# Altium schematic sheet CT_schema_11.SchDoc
size 391 x 385 mm
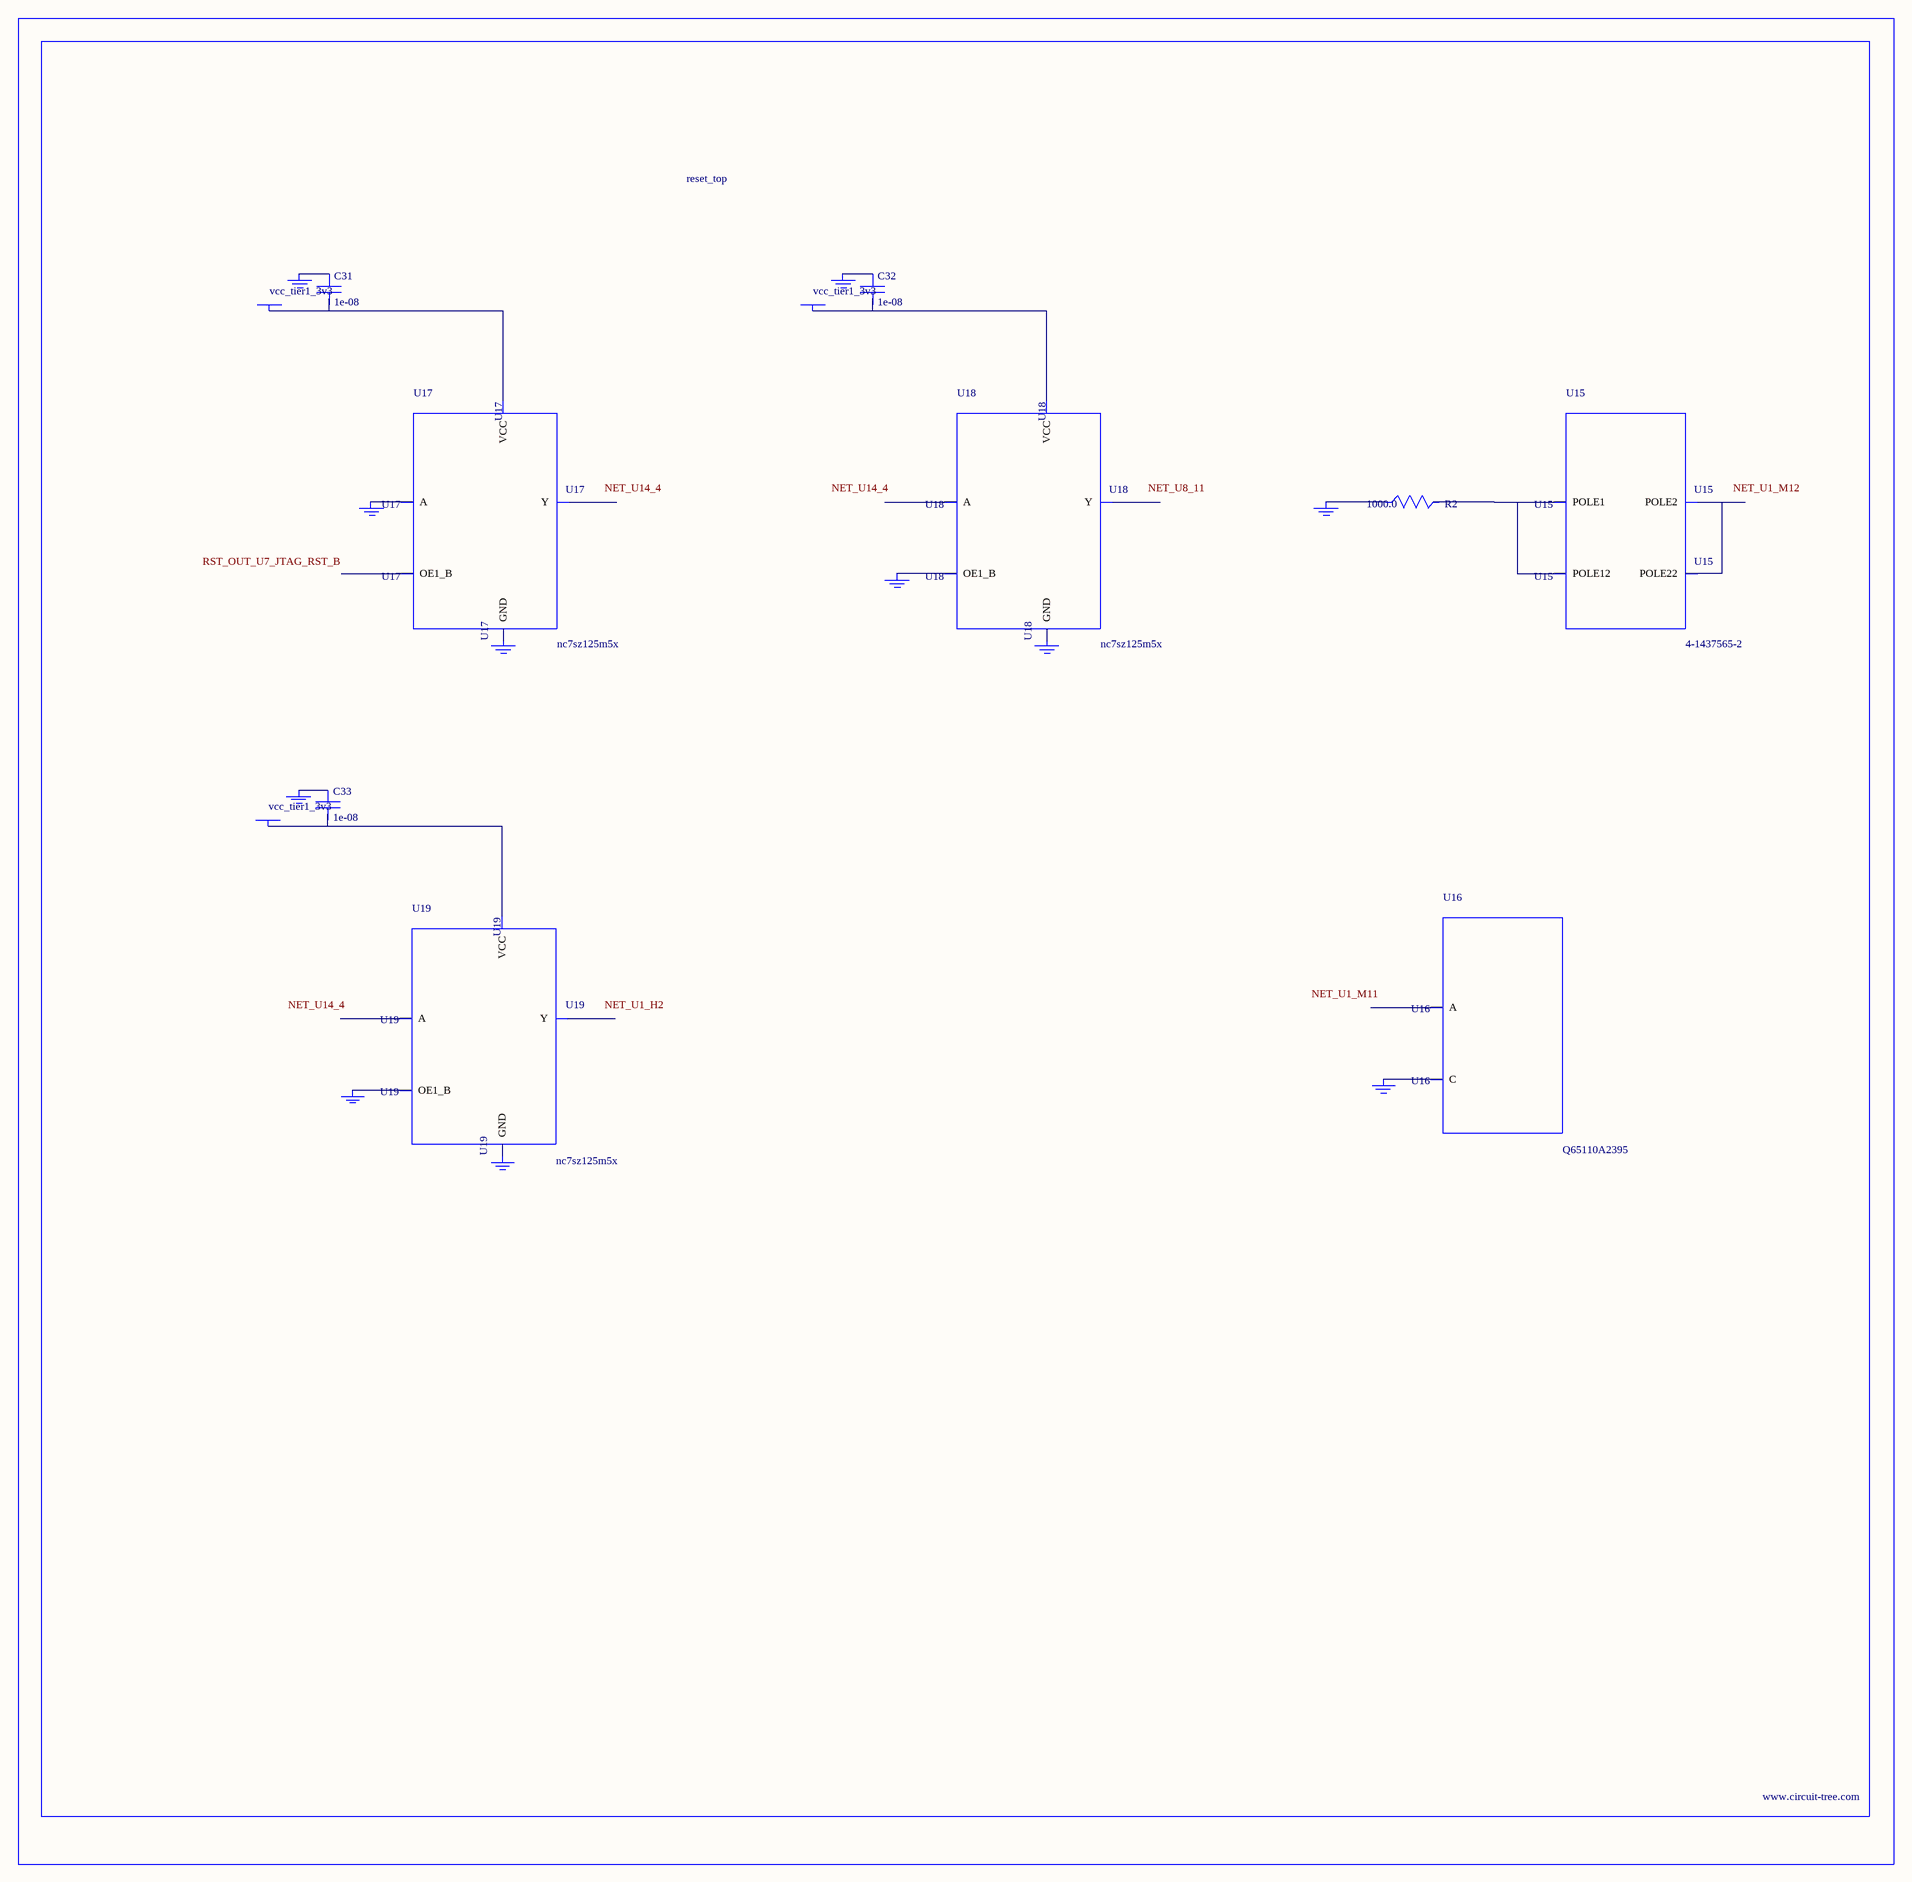
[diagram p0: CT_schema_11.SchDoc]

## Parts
BORDER10  (no value)
C31  1e-08  [C0402]
C32  1e-08  [C0402]
C33  1e-08  [C0402]
GND_INSTANCE_10_0  (no value)
GND_INSTANCE_10_1  (no value)
GND_INSTANCE_10_2  (no value)
GND_INSTANCE_10_3  (no value)
GND_INSTANCE_10_4  (no value)
GND_INSTANCE_10_5  (no value)
GND_INSTANCE_10_6  (no value)
GND_INSTANCE_10_7  (no value)
GND_INSTANCE_10_8  (no value)
GND_INSTANCE_10_9  (no value)
GND_INSTANCE_10_10  (no value)
POWER_INSTANCE_10_0  vcc_tier1_3v3
POWER_INSTANCE_10_1  vcc_tier1_3v3
POWER_INSTANCE_10_2  vcc_tier1_3v3
R2  1000.0  [R0603]
U15  4-1437565-2  [SW_4-1437565-2]
U16  Q65110A2395  [LGM67K-G1J2-24-Z]
U17  nc7sz125m5x  [NC7SZ125M5X]
U18  nc7sz125m5x  [NC7SZ125M5X]
U19  nc7sz125m5x  [NC7SZ125M5X]

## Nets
NetC31_1: C31.1 GND_INSTANCE_10_2.0(GND)
NetC31_2: C31.2 POWER_INSTANCE_10_0.0(PWR) U17.5(VCC)
NetC32_1: C32.1 GND_INSTANCE_10_5.0(GND)
NetC32_2: C32.2 POWER_INSTANCE_10_1.0(PWR) U18.5(VCC)
NetC33_1: C33.1 GND_INSTANCE_10_8.0(GND)
NetC33_2: C33.2 POWER_INSTANCE_10_2.0(PWR) U19.5(VCC)
NetGND_INSTANCE_10_0_0: GND_INSTANCE_10_0.0(GND) R2.1
NetGND_INSTANCE_10_1_0: GND_INSTANCE_10_1.0(GND) U16.C
NetGND_INSTANCE_10_3_0: GND_INSTANCE_10_3.0(GND) U17.2(A)
NetGND_INSTANCE_10_4_0: GND_INSTANCE_10_4.0(GND) U17.3(GND)
NetGND_INSTANCE_10_6_0: GND_INSTANCE_10_6.0(GND) U18.1(OE1_B)
NetGND_INSTANCE_10_7_0: GND_INSTANCE_10_7.0(GND) U18.3(GND)
NetGND_INSTANCE_10_9_0: GND_INSTANCE_10_9.0(GND) U19.1(OE1_B)
NetGND_INSTANCE_10_10_0: GND_INSTANCE_10_10.0(GND) U19.3(GND)
NetR2_2: R2.2 U15.1(POLE1) U15.2(POLE12)
NetU15_3: U15.3(POLE2) U15.4(POLE22)

Not connected (* = marked no-connect by the designer): U16 A; U17 1(OE1_B) 4(Y); U18 2(A) 4(Y); U19 2(A) 4(Y)

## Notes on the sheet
- Labels drawn without touching a wire or pin: NET_U1_H2, NET_U1_M11, NET_U1_M12, NET_U8_11, NET_U14_4, RST_OUT_U7_JTAG_RST_B

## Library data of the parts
BORDER10 = BORDER_PAGE10
C31-C33 = C0402C103K3RAC
GND_INSTANCE_10_0-GND_INSTANCE_10_10 = GND
POWER_INSTANCE_10_0-POWER_INSTANCE_10_2 = PWR
R2 = RC0603JR-071KL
